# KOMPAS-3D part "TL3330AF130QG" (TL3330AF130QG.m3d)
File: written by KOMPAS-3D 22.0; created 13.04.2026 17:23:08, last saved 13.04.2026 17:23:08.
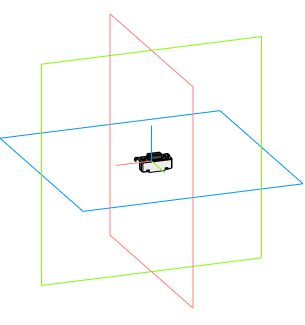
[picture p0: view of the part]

Document properties: Автор: Andrey; Полное имя файла: C:\Users\User1\Documents\TL3330AF130QG.m3d

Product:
- Part/product: TL3330AF130QG

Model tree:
1. Операция без истории:1
2. Операция без истории:2
3. Операция без истории:3
4. Операция без истории:4
5. Операция без истории:5
6. Операция без истории:6
7. Операция без истории:7
8. Операция без истории:8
